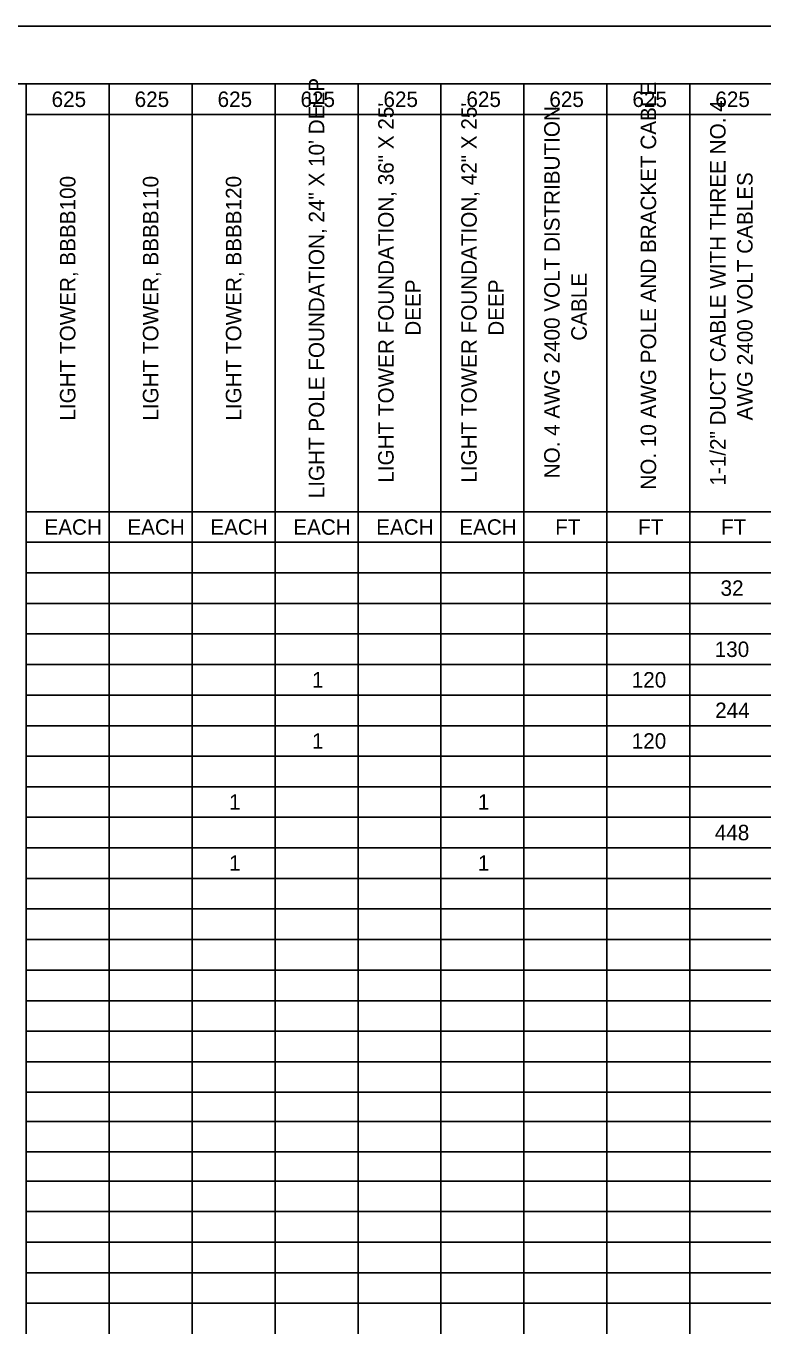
# Model space of a CAD drawing. Extents: x 0 to 34, y 0 to 22.
# Drawn here: x 13.35 to 19.72, y 10.69 to 22 of the extents above; entities that cross this region are included whole.
import ezdxf

# ---------------------------------------------------------------- set-up
doc = ezdxf.new("R2010")
doc.units = 0
for name, color, linetype in [('SH_Border', 7, 'Continuous'), ('SH_Cut_Line', 7, 'Continuous'), ('SH_Text', 7, 'Continuous')]:
    doc.layers.add(name, color=color, linetype=linetype)

msp = doc.modelspace()

# ---------------------------------------------------------------- linework, layer by layer
at = {"layer": 'SH_Border'}
msp.add_lwpolyline([(1.5, 21.5), (33.5, 21.5), (33.5, 0.5), (1.5, 0.5)], close=True, dxfattribs=at)
at = {"layer": 'SH_Cut_Line'}
msp.add_lwpolyline([(0, 0), (34, 0), (34, 22), (0, 22)], close=True, dxfattribs=at)
at = {"layer": 'SH_Text'}
for p, q in [((13.352, 21.5), (14.069, 21.5)), ((13.352, 21.5), (13.352, 21.236)), ((14.069, 21.5), (15.504, 21.5)), ((14.069, 21.5), (14.069, 21.236)), ((14.787, 21.5), (14.787, 21.236)), ((15.504, 21.5), (21.958, 21.5)), ((15.504, 21.5), (15.504, 21.236)), ((16.221, 21.5), (16.221, 21.236)), ((16.938, 21.5), (16.938, 21.236)), ((17.655, 21.5), (17.655, 21.236)), ((18.372, 21.5), (18.372, 21.236)), ((19.09, 21.5), (19.09, 21.236)), ((13.352, 21.236), (14.069, 21.236)), ((13.352, 21.236), (13.352, 20.972)), ((14.069, 21.236), (15.504, 21.236)), ((14.069, 21.236), (14.069, 20.972)), ((14.787, 21.236), (14.787, 20.972)), ((15.504, 21.236), (21.958, 21.236)), ((15.504, 21.236), (15.504, 20.972)), ((16.221, 21.236), (16.221, 20.972)), ((16.938, 21.236), (16.938, 20.972)), ((17.655, 21.236), (17.655, 20.972)), ((18.372, 21.236), (18.372, 20.972)), ((19.09, 21.236), (19.09, 20.972)), ((13.352, 20.972), (13.352, 20.707)), ((14.069, 20.972), (14.069, 20.707)), ((14.787, 20.972), (14.787, 20.707)), ((15.504, 20.972), (15.504, 20.707)), ((16.221, 20.972), (16.221, 20.707)), ((16.938, 20.972), (16.938, 20.707)), ((17.655, 20.972), (17.655, 20.707)), ((18.372, 20.972), (18.372, 20.707)), ((19.09, 20.972), (19.09, 20.707)), ((13.352, 20.707), (13.352, 20.443)), ((14.069, 20.707), (14.069, 20.443)), ((14.787, 20.707), (14.787, 20.443)), ((15.504, 20.707), (15.504, 20.443)), ((16.221, 20.707), (16.221, 20.443)), ((16.938, 20.707), (16.938, 20.443)), ((17.655, 20.707), (17.655, 20.443)), ((18.372, 20.707), (18.372, 20.443)), ((19.09, 20.707), (19.09, 20.443)), ((13.352, 20.443), (13.352, 20.179)), ((14.069, 20.443), (14.069, 20.179)), ((14.787, 20.443), (14.787, 20.179)), ((15.504, 20.443), (15.504, 20.179)), ((16.221, 20.443), (16.221, 20.179)), ((16.938, 20.443), (16.938, 20.179)), ((17.655, 20.443), (17.655, 20.179)), ((18.372, 20.443), (18.372, 20.179)), ((19.09, 20.443), (19.09, 20.179)), ((13.352, 20.179), (13.352, 19.915)), ((14.069, 20.179), (14.069, 19.915)), ((14.787, 20.179), (14.787, 19.915)), ((15.504, 20.179), (15.504, 19.915)), ((16.221, 20.179), (16.221, 19.915)), ((16.938, 20.179), (16.938, 19.915)), ((17.655, 20.179), (17.655, 19.915)), ((18.372, 20.179), (18.372, 19.915)), ((19.09, 20.179), (19.09, 19.915)), ((13.352, 19.915), (13.352, 19.651)), ((14.069, 19.915), (14.069, 19.651)), ((14.787, 19.915), (14.787, 19.651)), ((15.504, 19.915), (15.504, 19.651)), ((16.221, 19.915), (16.221, 19.651)), ((16.938, 19.915), (16.938, 19.651)), ((17.655, 19.915), (17.655, 19.651)), ((18.372, 19.915), (18.372, 19.651)), ((19.09, 19.915), (19.09, 19.651)), ((13.352, 19.651), (13.352, 19.386)), ((14.069, 19.651), (14.069, 19.386)), ((14.787, 19.651), (14.787, 19.386)), ((15.504, 19.651), (15.504, 19.386)), ((16.221, 19.651), (16.221, 19.386)), ((16.938, 19.651), (16.938, 19.386)), ((17.655, 19.651), (17.655, 19.386)), ((18.372, 19.651), (18.372, 19.386)), ((19.09, 19.651), (19.09, 19.386)), ((13.352, 19.386), (13.352, 19.122)), ((14.069, 19.386), (14.069, 19.122)), ((14.787, 19.386), (14.787, 19.122)), ((15.504, 19.386), (15.504, 19.122)), ((16.221, 19.386), (16.221, 19.122)), ((16.938, 19.386), (16.938, 19.122)), ((17.655, 19.386), (17.655, 19.122)), ((18.372, 19.386), (18.372, 19.122)), ((19.09, 19.386), (19.09, 19.122)), ((13.352, 19.122), (13.352, 18.858)), ((14.069, 19.122), (14.069, 18.858)), ((14.787, 19.122), (14.787, 18.858)), ((15.504, 19.122), (15.504, 18.858)), ((16.221, 19.122), (16.221, 18.858)), ((16.938, 19.122), (16.938, 18.858)), ((17.655, 19.122), (17.655, 18.858)), ((18.372, 19.122), (18.372, 18.858)), ((19.09, 19.122), (19.09, 18.858)), ((13.352, 18.858), (13.352, 18.594)), ((14.069, 18.858), (14.069, 18.594)), ((14.787, 18.858), (14.787, 18.594)), ((15.504, 18.858), (15.504, 18.594)), ((16.221, 18.858), (16.221, 18.594)), ((16.938, 18.858), (16.938, 18.594)), ((17.655, 18.858), (17.655, 18.594)), ((18.372, 18.858), (18.372, 18.594)), ((19.09, 18.858), (19.09, 18.594)), ((13.352, 18.594), (13.352, 18.329)), ((14.069, 18.594), (14.069, 18.329)), ((14.787, 18.594), (14.787, 18.329)), ((15.504, 18.594), (15.504, 18.329)), ((16.221, 18.594), (16.221, 18.329)), ((16.938, 18.594), (16.938, 18.329)), ((17.655, 18.594), (17.655, 18.329)), ((18.372, 18.594), (18.372, 18.329)), ((19.09, 18.594), (19.09, 18.329)), ((13.352, 18.329), (13.352, 18.065)), ((14.069, 18.329), (14.069, 18.065)), ((14.787, 18.329), (14.787, 18.065)), ((15.504, 18.329), (15.504, 18.065)), ((16.221, 18.329), (16.221, 18.065)), ((16.938, 18.329), (16.938, 18.065)), ((17.655, 18.329), (17.655, 18.065)), ((18.372, 18.329), (18.372, 18.065)), ((19.09, 18.329), (19.09, 18.065)), ((13.352, 18.065), (13.352, 17.801)), ((14.069, 18.065), (14.069, 17.801)), ((14.787, 18.065), (14.787, 17.801)), ((15.504, 18.065), (15.504, 17.801)), ((16.221, 18.065), (16.221, 17.801)), ((16.938, 18.065), (16.938, 17.801)), ((17.655, 18.065), (17.655, 17.801)), ((18.372, 18.065), (18.372, 17.801)), ((19.09, 18.065), (19.09, 17.801)), ((13.352, 17.801), (14.069, 17.801)), ((13.352, 17.801), (13.352, 17.537)), ((14.069, 17.801), (15.504, 17.801)), ((14.069, 17.801), (14.069, 17.537)), ((14.787, 17.801), (14.787, 17.537)), ((15.504, 17.801), (21.958, 17.801)), ((15.504, 17.801), (15.504, 17.537)), ((16.221, 17.801), (16.221, 17.537)), ((16.938, 17.801), (16.938, 17.537)), ((17.655, 17.801), (17.655, 17.537)), ((18.372, 17.801), (18.372, 17.537)), ((19.09, 17.801), (19.09, 17.537)), ((13.352, 17.537), (14.069, 17.537)), ((13.352, 17.537), (13.352, 17.273)), ((14.069, 17.537), (15.504, 17.537)), ((14.069, 17.537), (14.069, 17.273)), ((14.787, 17.537), (14.787, 17.273)), ((15.504, 17.537), (21.958, 17.537)), ((15.504, 17.537), (15.504, 17.273)), ((16.221, 17.537), (16.221, 17.273)), ((16.938, 17.537), (16.938, 17.273)), ((17.655, 17.537), (17.655, 17.273)), ((18.372, 17.537), (18.372, 17.273)), ((19.09, 17.537), (19.09, 17.273)), ((13.352, 17.273), (14.069, 17.273)), ((13.352, 17.273), (13.352, 17.008)), ((14.069, 17.273), (15.504, 17.273)), ((14.069, 17.273), (14.069, 17.008)), ((14.787, 17.273), (14.787, 17.008)), ((15.504, 17.273), (21.958, 17.273)), ((15.504, 17.273), (15.504, 17.008)), ((16.221, 17.273), (16.221, 17.008)), ((16.938, 17.273), (16.938, 17.008)), ((17.655, 17.273), (17.655, 17.008)), ((18.372, 17.273), (18.372, 17.008)), ((19.09, 17.273), (19.09, 17.008)), ((13.352, 17.008), (14.069, 17.008)), ((13.352, 17.008), (13.352, 16.744)), ((14.069, 17.008), (15.504, 17.008)), ((14.069, 17.008), (14.069, 16.744)), ((14.787, 17.008), (14.787, 16.744)), ((15.504, 17.008), (21.958, 17.008)), ((15.504, 17.008), (15.504, 16.744)), ((16.221, 17.008), (16.221, 16.744)), ((16.938, 17.008), (16.938, 16.744)), ((17.655, 17.008), (17.655, 16.744)), ((18.372, 17.008), (18.372, 16.744)), ((19.09, 17.008), (19.09, 16.744)), ((13.352, 16.744), (14.069, 16.744)), ((13.352, 16.744), (13.352, 16.48)), ((14.069, 16.744), (15.504, 16.744)), ((14.069, 16.744), (14.069, 16.48)), ((14.787, 16.744), (14.787, 16.48)), ((15.504, 16.744), (21.958, 16.744)), ((15.504, 16.744), (15.504, 16.48)), ((16.221, 16.744), (16.221, 16.48)), ((16.938, 16.744), (16.938, 16.48)), ((17.655, 16.744), (17.655, 16.48)), ((18.372, 16.744), (18.372, 16.48)), ((19.09, 16.744), (19.09, 16.48)), ((13.352, 16.48), (14.069, 16.48)), ((13.352, 16.48), (13.352, 16.216)), ((14.069, 16.48), (15.504, 16.48)), ((14.069, 16.48), (14.069, 16.216)), ((14.787, 16.48), (14.787, 16.216)), ((15.504, 16.48), (21.958, 16.48)), ((15.504, 16.48), (15.504, 16.216)), ((16.221, 16.48), (16.221, 16.216)), ((16.938, 16.48), (16.938, 16.216)), ((17.655, 16.48), (17.655, 16.216)), ((18.372, 16.48), (18.372, 16.216)), ((19.09, 16.48), (19.09, 16.216)), ((13.352, 16.216), (14.069, 16.216)), ((13.352, 16.216), (13.352, 15.951)), ((14.069, 16.216), (15.504, 16.216)), ((14.069, 16.216), (14.069, 15.951)), ((14.787, 16.216), (14.787, 15.951)), ((15.504, 16.216), (21.958, 16.216)), ((15.504, 16.216), (15.504, 15.951)), ((16.221, 16.216), (16.221, 15.951)), ((16.938, 16.216), (16.938, 15.951)), ((17.655, 16.216), (17.655, 15.951)), ((18.372, 16.216), (18.372, 15.951)), ((19.09, 16.216), (19.09, 15.951)), ((13.352, 15.951), (14.069, 15.951)), ((13.352, 15.951), (13.352, 15.687)), ((14.069, 15.951), (15.504, 15.951)), ((14.069, 15.951), (14.069, 15.687)), ((14.787, 15.951), (14.787, 15.687)), ((15.504, 15.951), (21.958, 15.951)), ((15.504, 15.951), (15.504, 15.687)), ((16.221, 15.951), (16.221, 15.687)), ((16.938, 15.951), (16.938, 15.687)), ((17.655, 15.951), (17.655, 15.687)), ((18.372, 15.951), (18.372, 15.687)), ((19.09, 15.951), (19.09, 15.687)), ((13.352, 15.687), (14.069, 15.687)), ((13.352, 15.687), (13.352, 15.423)), ((14.069, 15.687), (15.504, 15.687)), ((14.069, 15.687), (14.069, 15.423)), ((14.787, 15.687), (14.787, 15.423)), ((15.504, 15.687), (21.958, 15.687)), ((15.504, 15.687), (15.504, 15.423)), ((16.221, 15.687), (16.221, 15.423)), ((16.938, 15.687), (16.938, 15.423)), ((17.655, 15.687), (17.655, 15.423)), ((18.372, 15.687), (18.372, 15.423)), ((19.09, 15.687), (19.09, 15.423)), ((13.352, 15.423), (14.069, 15.423)), ((13.352, 15.423), (13.352, 15.159)), ((14.069, 15.423), (15.504, 15.423)), ((14.069, 15.423), (14.069, 15.159)), ((14.787, 15.423), (14.787, 15.159)), ((15.504, 15.423), (21.958, 15.423)), ((15.504, 15.423), (15.504, 15.159)), ((16.221, 15.423), (16.221, 15.159)), ((16.938, 15.423), (16.938, 15.159)), ((17.655, 15.423), (17.655, 15.159)), ((18.372, 15.423), (18.372, 15.159)), ((19.09, 15.423), (19.09, 15.159)), ((13.352, 15.159), (14.069, 15.159)), ((13.352, 15.159), (13.352, 14.895)), ((14.069, 15.159), (15.504, 15.159)), ((14.069, 15.159), (14.069, 14.895)), ((14.787, 15.159), (14.787, 14.895)), ((15.504, 15.159), (21.958, 15.159)), ((15.504, 15.159), (15.504, 14.895)), ((16.221, 15.159), (16.221, 14.895)), ((16.938, 15.159), (16.938, 14.895)), ((17.655, 15.159), (17.655, 14.895)), ((18.372, 15.159), (18.372, 14.895)), ((19.09, 15.159), (19.09, 14.895)), ((13.352, 14.895), (14.069, 14.895)), ((13.352, 14.895), (13.352, 14.63)), ((14.069, 14.895), (15.504, 14.895)), ((14.069, 14.895), (14.069, 14.63)), ((14.787, 14.895), (14.787, 14.63)), ((15.504, 14.895), (21.958, 14.895)), ((15.504, 14.895), (15.504, 14.63)), ((16.221, 14.895), (16.221, 14.63)), ((16.938, 14.895), (16.938, 14.63)), ((17.655, 14.895), (17.655, 14.63)), ((18.372, 14.895), (18.372, 14.63)), ((19.09, 14.895), (19.09, 14.63)), ((13.352, 14.63), (14.069, 14.63)), ((13.352, 14.63), (13.352, 14.366)), ((14.069, 14.63), (15.504, 14.63)), ((14.069, 14.63), (14.069, 14.366)), ((14.787, 14.63), (14.787, 14.366)), ((15.504, 14.63), (21.958, 14.63)), ((15.504, 14.63), (15.504, 14.366)), ((16.221, 14.63), (16.221, 14.366)), ((16.938, 14.63), (16.938, 14.366)), ((17.655, 14.63), (17.655, 14.366)), ((18.372, 14.63), (18.372, 14.366)), ((19.09, 14.63), (19.09, 14.366)), ((13.352, 14.366), (14.069, 14.366)), ((13.352, 14.366), (13.352, 14.102)), ((14.069, 14.366), (15.504, 14.366)), ((14.069, 14.366), (14.069, 14.102)), ((14.787, 14.366), (14.787, 14.102)), ((15.504, 14.366), (21.958, 14.366)), ((15.504, 14.366), (15.504, 14.102)), ((16.221, 14.366), (16.221, 14.102)), ((16.938, 14.366), (16.938, 14.102)), ((17.655, 14.366), (17.655, 14.102)), ((18.372, 14.366), (18.372, 14.102)), ((19.09, 14.366), (19.09, 14.102)), ((13.352, 14.102), (14.069, 14.102)), ((13.352, 14.102), (13.352, 13.838)), ((14.069, 14.102), (15.504, 14.102)), ((14.069, 14.102), (14.069, 13.838)), ((14.787, 14.102), (14.787, 13.838)), ((15.504, 14.102), (21.958, 14.102)), ((15.504, 14.102), (15.504, 13.838)), ((16.221, 14.102), (16.221, 13.838)), ((16.938, 14.102), (16.938, 13.838)), ((17.655, 14.102), (17.655, 13.838)), ((18.372, 14.102), (18.372, 13.838)), ((19.09, 14.102), (19.09, 13.838)), ((13.352, 13.838), (14.069, 13.838)), ((13.352, 13.838), (13.352, 13.573)), ((14.069, 13.838), (15.504, 13.838)), ((14.069, 13.838), (14.069, 13.573)), ((14.787, 13.838), (14.787, 13.573)), ((15.504, 13.838), (21.958, 13.838)), ((15.504, 13.838), (15.504, 13.573)), ((16.221, 13.838), (16.221, 13.573)), ((16.938, 13.838), (16.938, 13.573)), ((17.655, 13.838), (17.655, 13.573)), ((18.372, 13.838), (18.372, 13.573)), ((19.09, 13.838), (19.09, 13.573)), ((13.352, 13.573), (14.069, 13.573)), ((13.352, 13.573), (13.352, 13.309)), ((14.069, 13.573), (15.504, 13.573)), ((14.069, 13.573), (14.069, 13.309)), ((14.787, 13.573), (14.787, 13.309)), ((15.504, 13.573), (21.958, 13.573)), ((15.504, 13.573), (15.504, 13.309)), ((16.221, 13.573), (16.221, 13.309)), ((16.938, 13.573), (16.938, 13.309)), ((17.655, 13.573), (17.655, 13.309)), ((18.372, 13.573), (18.372, 13.309)), ((19.09, 13.573), (19.09, 13.309)), ((13.352, 13.309), (14.069, 13.309)), ((13.352, 13.309), (13.352, 13.045)), ((14.069, 13.309), (15.504, 13.309)), ((14.069, 13.309), (14.069, 13.045)), ((14.787, 13.309), (14.787, 13.045)), ((15.504, 13.309), (21.958, 13.309)), ((15.504, 13.309), (15.504, 13.045)), ((16.221, 13.309), (16.221, 13.045)), ((16.938, 13.309), (16.938, 13.045)), ((17.655, 13.309), (17.655, 13.045)), ((18.372, 13.309), (18.372, 13.045)), ((19.09, 13.309), (19.09, 13.045)), ((13.352, 13.045), (14.069, 13.045)), ((13.352, 13.045), (13.352, 12.781)), ((14.069, 13.045), (15.504, 13.045)), ((14.069, 13.045), (14.069, 12.781)), ((14.787, 13.045), (14.787, 12.781)), ((15.504, 13.045), (21.958, 13.045)), ((15.504, 13.045), (15.504, 12.781)), ((16.221, 13.045), (16.221, 12.781)), ((16.938, 13.045), (16.938, 12.781)), ((17.655, 13.045), (17.655, 12.781)), ((18.372, 13.045), (18.372, 12.781)), ((19.09, 13.045), (19.09, 12.781)), ((13.352, 12.781), (14.069, 12.781)), ((13.352, 12.781), (13.352, 12.265)), ((14.069, 12.781), (15.504, 12.781)), ((14.069, 12.781), (14.069, 12.265)), ((14.787, 12.781), (14.787, 12.265)), ((15.504, 12.781), (21.958, 12.781)), ((15.504, 12.781), (15.504, 12.265)), ((16.221, 12.781), (16.221, 12.265)), ((16.938, 12.781), (16.938, 12.265)), ((17.655, 12.781), (17.655, 12.265)), ((18.372, 12.781), (18.372, 12.265)), ((19.09, 12.781), (19.09, 12.265)), ((13.352, 12.529), (14.069, 12.529)), ((14.069, 12.529), (15.504, 12.529)), ((15.504, 12.529), (21.958, 12.529)), ((13.352, 12.265), (14.069, 12.265)), ((13.352, 12.265), (13.352, 11.749)), ((14.069, 12.265), (15.504, 12.265)), ((14.069, 12.265), (14.069, 11.749)), ((14.787, 12.265), (14.787, 11.749)), ((15.504, 12.265), (21.958, 12.265)), ((15.504, 12.265), (15.504, 11.749)), ((16.221, 12.265), (16.221, 11.749)), ((16.938, 12.265), (16.938, 11.749)), ((17.655, 12.265), (17.655, 11.749)), ((18.372, 12.265), (18.372, 11.749)), ((19.09, 12.265), (19.09, 11.749)), ((13.352, 12.013), (14.069, 12.013)), ((14.069, 12.013), (15.504, 12.013)), ((15.504, 12.013), (21.958, 12.013)), ((13.352, 11.749), (14.069, 11.749)), ((13.352, 11.749), (13.352, 11.485)), ((14.069, 11.749), (15.504, 11.749)), ((14.069, 11.749), (14.069, 11.485)), ((14.787, 11.749), (14.787, 11.485)), ((15.504, 11.749), (21.958, 11.749)), ((15.504, 11.749), (15.504, 11.485)), ((16.221, 11.749), (16.221, 11.485)), ((16.938, 11.749), (16.938, 11.485)), ((17.655, 11.749), (17.655, 11.485)), ((18.372, 11.749), (18.372, 11.485)), ((19.09, 11.749), (19.09, 11.485)), ((13.352, 11.485), (14.069, 11.485)), ((13.352, 11.485), (13.352, 11.221)), ((14.069, 11.485), (15.504, 11.485)), ((14.069, 11.485), (14.069, 11.221)), ((14.787, 11.485), (14.787, 11.221)), ((15.504, 11.485), (21.958, 11.485)), ((15.504, 11.485), (15.504, 11.221)), ((16.221, 11.485), (16.221, 11.221)), ((16.938, 11.485), (16.938, 11.221)), ((17.655, 11.485), (17.655, 11.221)), ((18.372, 11.485), (18.372, 11.221)), ((19.09, 11.485), (19.09, 11.221)), ((13.352, 11.221), (14.069, 11.221)), ((13.352, 11.221), (13.352, 10.956)), ((14.069, 11.221), (15.504, 11.221)), ((14.069, 11.221), (14.069, 10.956)), ((14.787, 11.221), (14.787, 10.956)), ((15.504, 11.221), (21.958, 11.221)), ((15.504, 11.221), (15.504, 10.956)), ((16.221, 11.221), (16.221, 10.956)), ((16.938, 11.221), (16.938, 10.956)), ((17.655, 11.221), (17.655, 10.956)), ((18.372, 11.221), (18.372, 10.956)), ((19.09, 11.221), (19.09, 10.956)), ((13.352, 10.956), (14.069, 10.956)), ((13.352, 10.956), (13.352, 10.692)), ((14.069, 10.956), (15.504, 10.956)), ((14.069, 10.956), (14.069, 10.692)), ((14.787, 10.956), (14.787, 10.692)), ((15.504, 10.956), (21.958, 10.956)), ((15.504, 10.956), (15.504, 10.692)), ((16.221, 10.956), (16.221, 10.692)), ((16.938, 10.956), (16.938, 10.692)), ((17.655, 10.956), (17.655, 10.692)), ((18.372, 10.956), (18.372, 10.692)), ((19.09, 10.956), (19.09, 10.692))]:
    msp.add_line(p, q, dxfattribs=at)

# ---------------------------------------------------------------- texts
for s, height, p in [('LIGHT POLE FOUNDATION, 24" X 10\' DEEP', 0.13368, (15.929, 17.918)), ('NO. 10 AWG POLE AND BRACKET CABLE', 0.13368, (18.798, 17.992)), ('LIGHT TOWER FOUNDATION, 36" X 25\' ', 0.13368, (16.529, 18.052)), ('LIGHT TOWER FOUNDATION, 42" X 25\' ', 0.13368, (17.247, 18.052)), ('NO. 4 AWG 2400 VOLT DISTRIBUTION ', 0.13368, (17.964, 18.09)), ('1-1/2" DUCT CABLE WITH THREE NO. 4 ', 0.13368, (19.398, 18.027)), ('LIGHT TOWER, BBBB100', 0.13368, (13.778, 18.589)), ('LIGHT TOWER, BBBB110', 0.13368, (14.495, 18.589)), ('LIGHT TOWER, BBBB120', 0.13368, (15.212, 18.589)), ('AWG 2400 VOLT CABLES', 0.13368, (19.632, 18.591)), ('DEEP', 0.1337, (16.763, 19.323)), ('DEEP', 0.1337, (17.481, 19.323)), ('CABLE', 0.1337, (18.198, 19.28))]:
    msp.add_text(s, height=height, rotation=90, dxfattribs=at).set_placement(p)
for s, height, p in [('625', 0.1337, (13.572, 21.301)), ('625', 0.1337, (14.29, 21.301)), ('625', 0.1337, (15.007, 21.301)), ('625', 0.1337, (15.724, 21.301)), ('625', 0.1337, (16.441, 21.301)), ('625', 0.1337, (17.158, 21.301)), ('625', 0.1337, (17.875, 21.301)), ('625', 0.1337, (18.593, 21.301)), ('625', 0.1337, (19.31, 21.301)), ('EACH', 0.1337, (13.51, 17.602)), ('EACH', 0.1337, (14.227, 17.602)), ('EACH', 0.1337, (14.944, 17.602)), ('EACH', 0.1337, (15.661, 17.602)), ('EACH', 0.1337, (16.378, 17.602)), ('EACH', 0.1337, (17.096, 17.602)), ('FT', 0.1337, (17.925, 17.602)), ('FT', 0.1337, (18.642, 17.602)), ('FT', 0.1337, (19.359, 17.602)), ('32', 0.1337, (19.355, 17.074)), ('130', 0.1337, (19.304, 16.545)), ('1', 0.134, (15.823, 16.281)), ('120', 0.1337, (18.587, 16.281)), ('244', 0.1337, (19.308, 16.017)), ('1', 0.134, (15.823, 15.752)), ('120', 0.1337, (18.587, 15.752)), ('1', 0.134, (15.106, 15.224)), ('1', 0.134, (17.257, 15.224)), ('448', 0.1337, (19.305, 14.96)), ('1', 0.134, (15.106, 14.696)), ('1', 0.134, (17.257, 14.696))]:
    msp.add_text(s, height=height, dxfattribs=at).set_placement(p)

doc.saveas('drawing.dxf')
